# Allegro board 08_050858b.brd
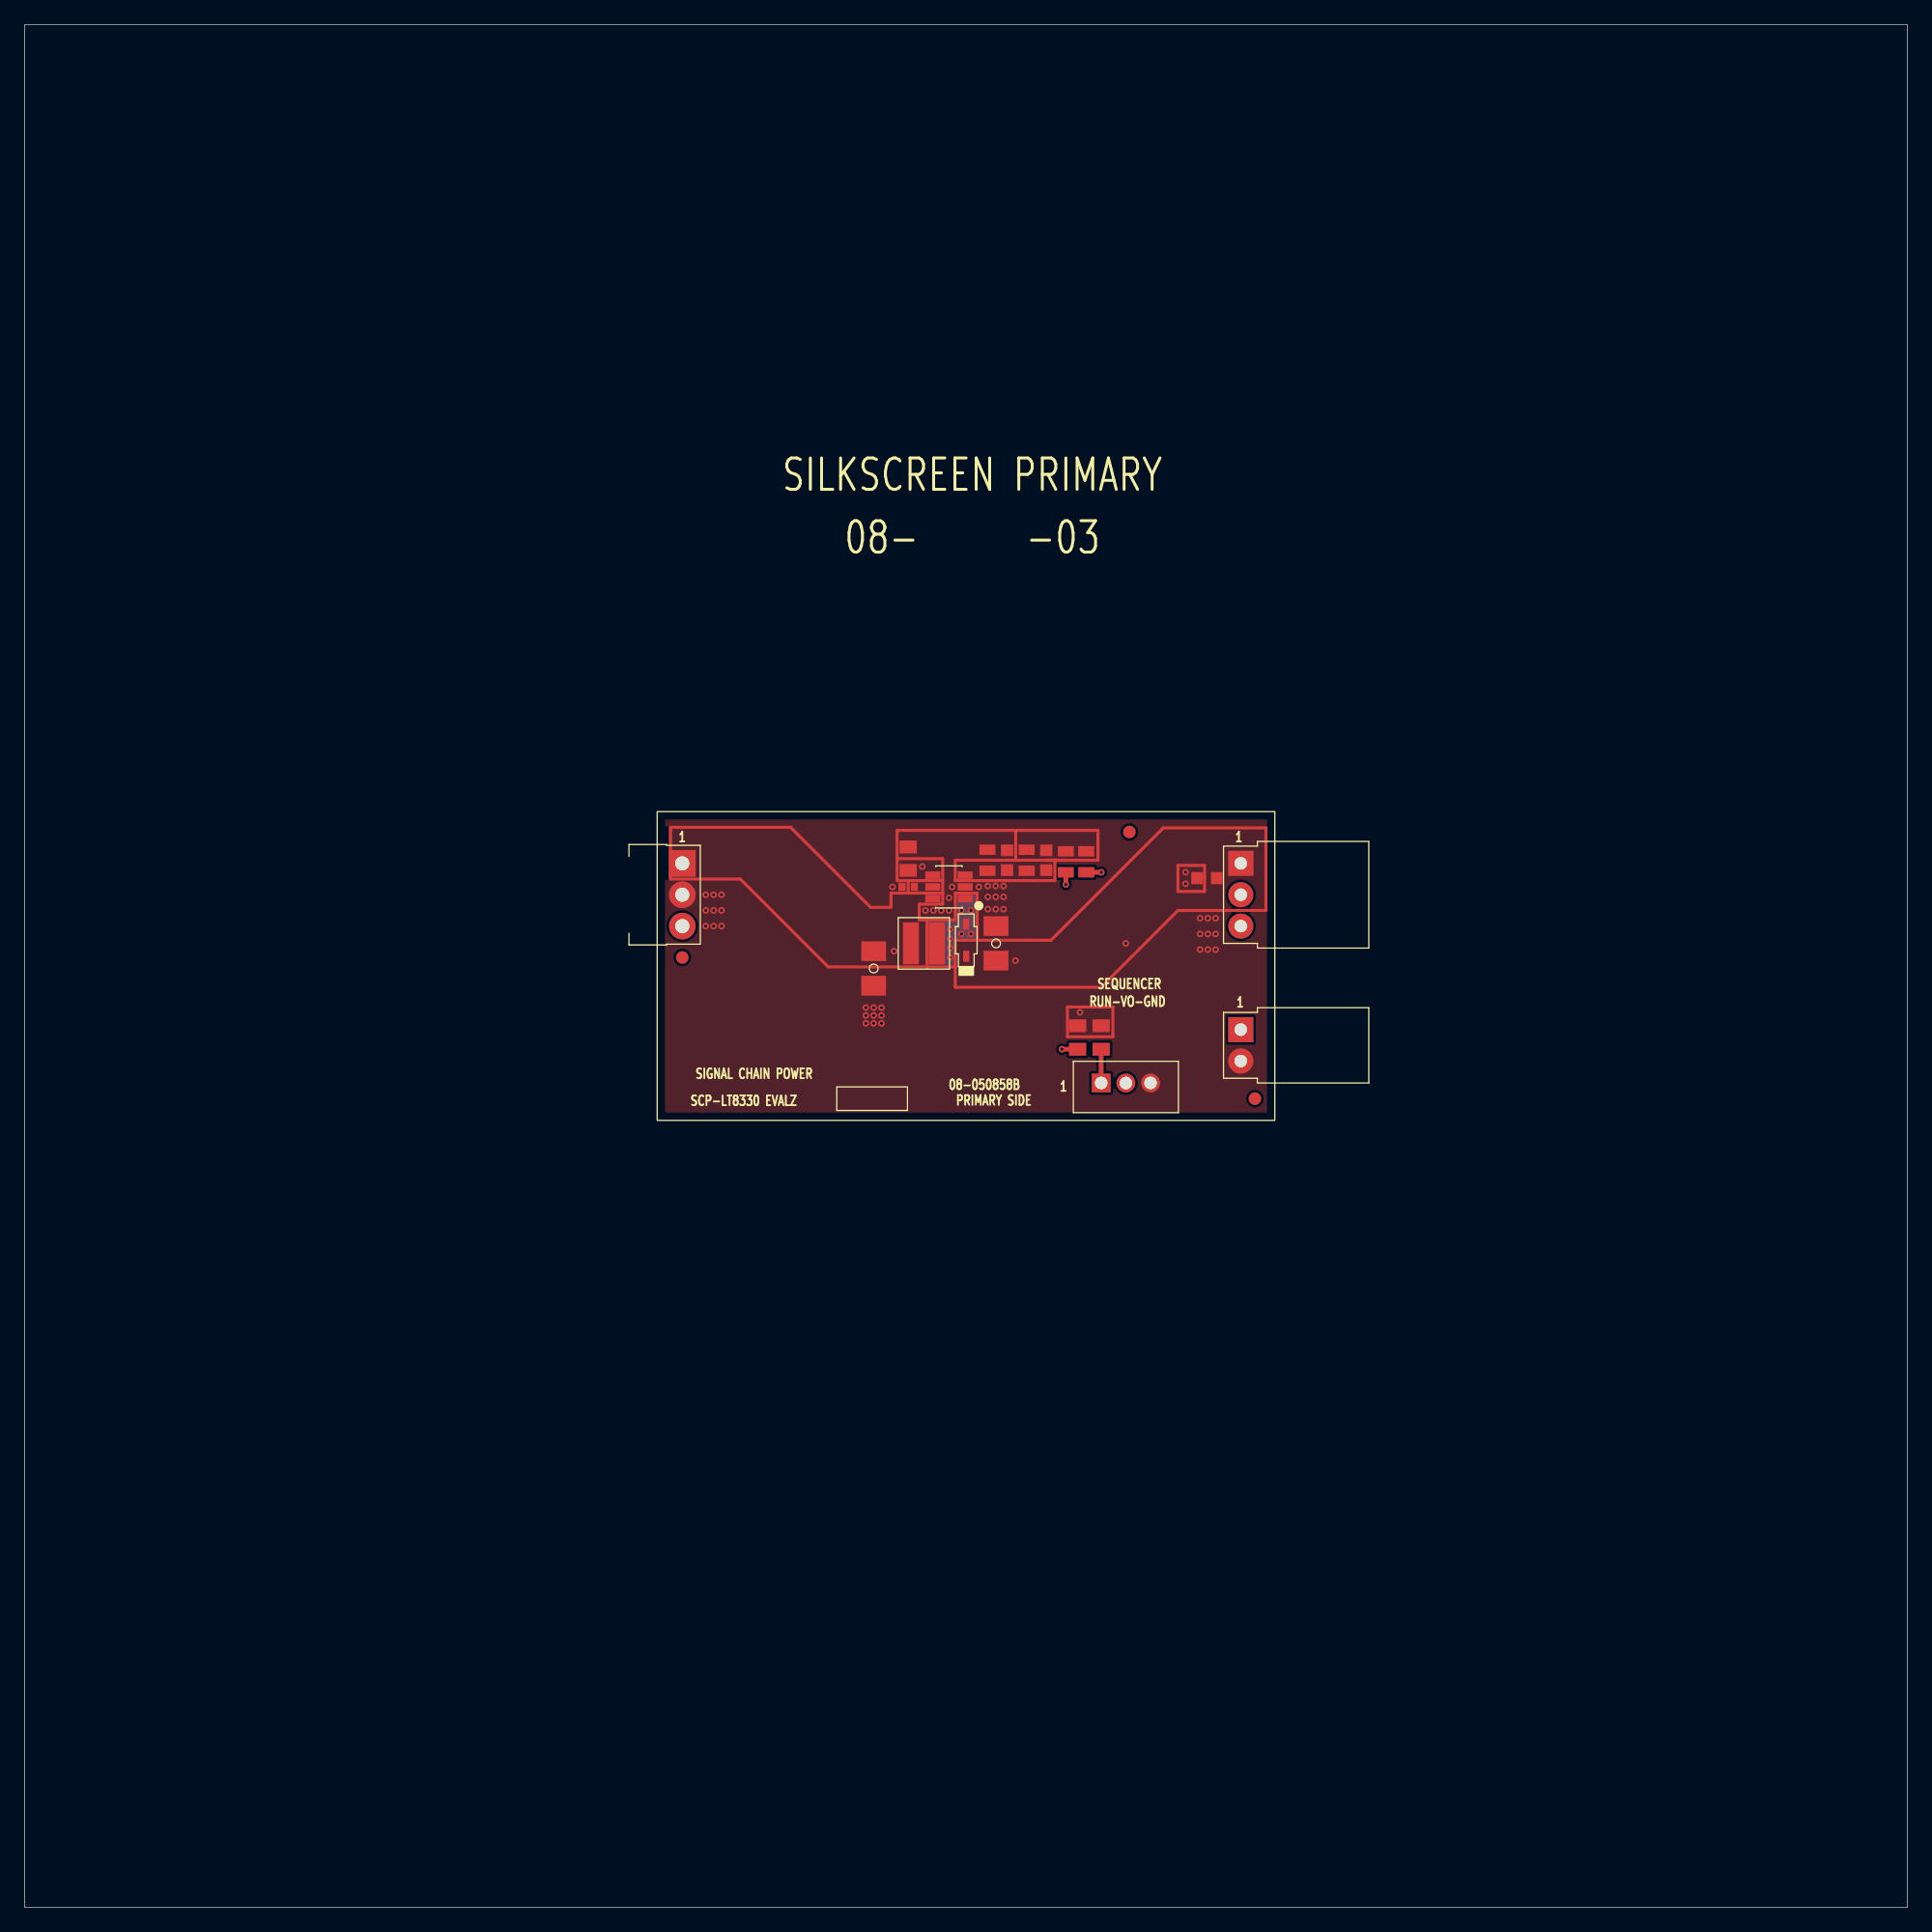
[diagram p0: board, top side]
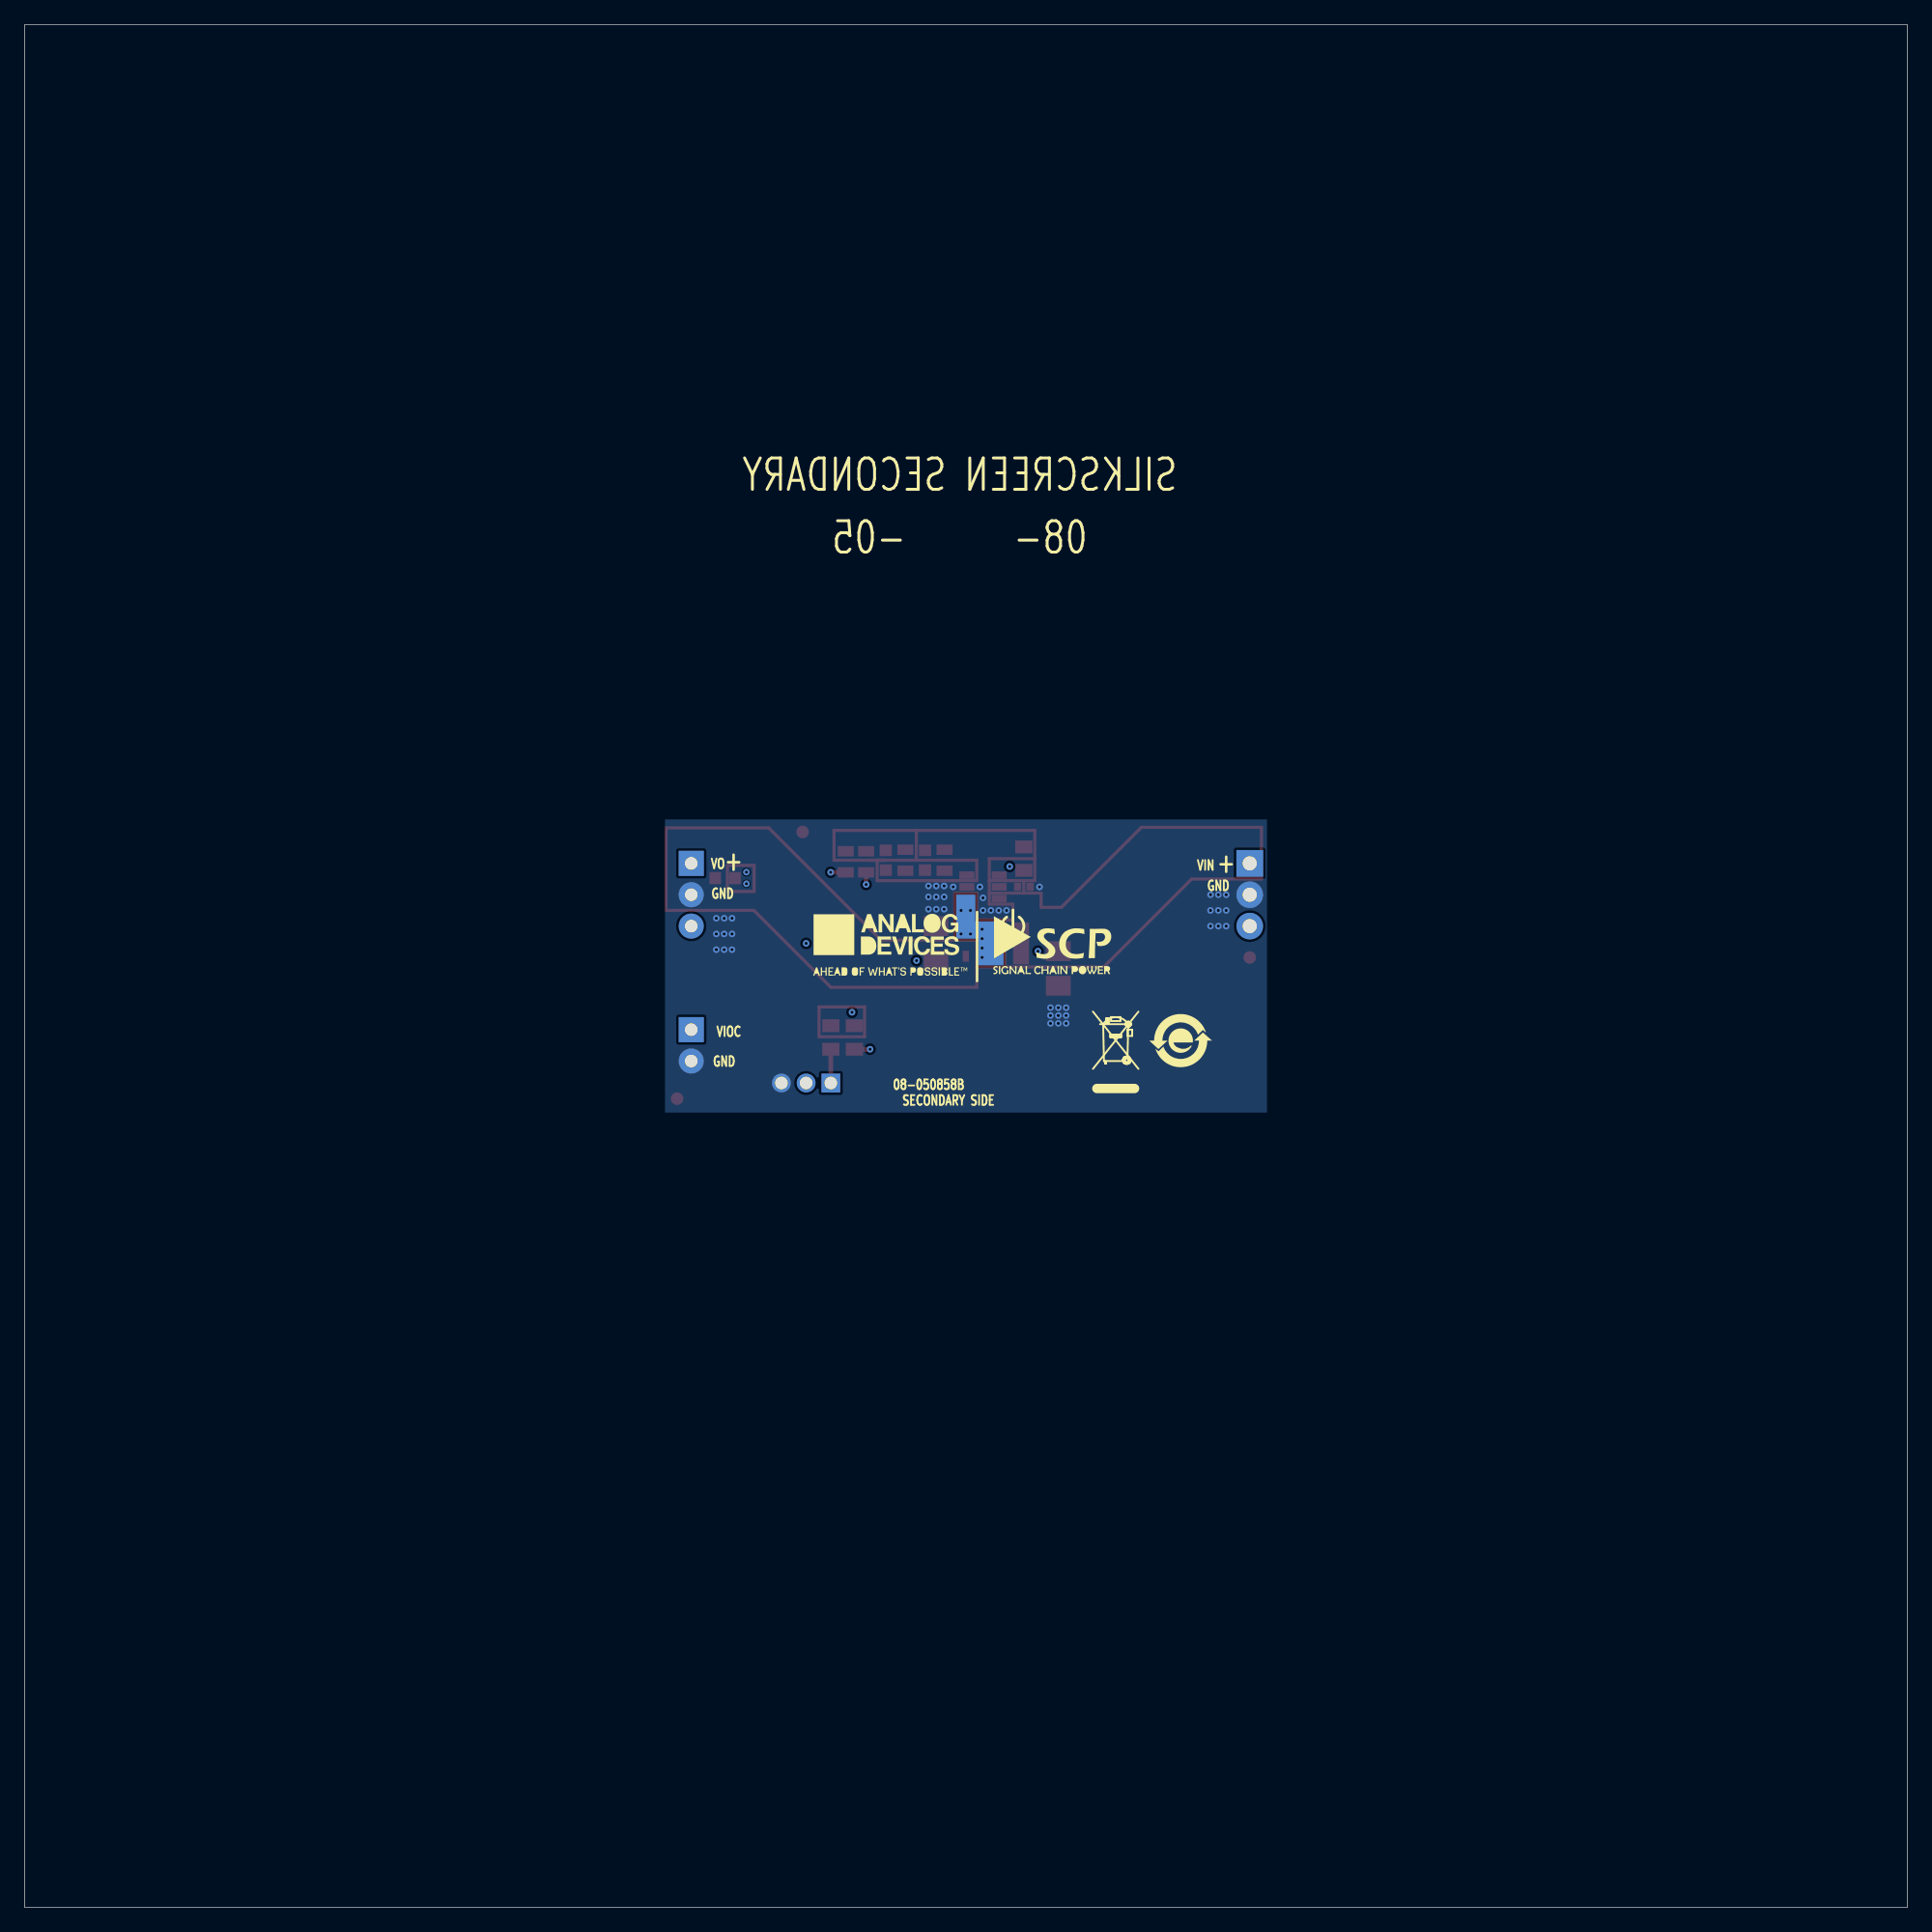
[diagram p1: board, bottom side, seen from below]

Outline 152.4 x 152.4 mm; copper layers: TOP, L2_AGND, L3_SIGNAL, BOTTOM. Coordinates in mm from the lower left corner of the outline.
Outline path: 0,152.4 152.4,152.4 152.4,0 0,0 0,152.4

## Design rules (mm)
constraint set DEFAULT: min track width 0.203

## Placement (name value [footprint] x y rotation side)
C1  4.7UF  [C1206H71]  68.73 76 270 top
C2  4.7UF  [C1206H71]  78.63 78.03 90 top
C3  1UF  [C0402]  71.52 82.6 180 top
C4  TBD0603  [C0603]  79.52 84.76 90 top
C8  4.7PF  [C0603]  82.7 84.76 270 top
C12  0.1UF  [C0603]  95.7 83.32 180 top
D1  PMEG6010CEJ  [SOD323F_B]  76.22 78.29 90 top
INPUT  PBC03SBAN  [CNTHMHDRRA1X3L300W100H145]  53.23 84.51 270 top
L1  6.8UH  [LSMSQ118H59_WE]  72.79 78.03 0 top
NOREF  -  []  101.19 63.71 90 top
NOREF#2  -  []  121.43 207.19 0 top
NOREF#3  -  []  51.18 88.77 270 top
NOREF#4  -  []  101.22 63.63 90 top
NOREF#5  -  []  51.18 63.63 0 top
NOREF#6  -  []  101.22 88.77 180 top
NOREF#7  -  [unnamed#2]  99.59 65.46 0 top
NOREF#8  -  []  -84.59 14.53 0 top
NOREF#9  -  []  -74.78 242.5 0 top
NOREF#10  -  []  -149.21 -137.49 0 top
NOREF#11  -  [unnamed#2]  53.23 76.89 0 top
NOREF#12  -  []  -298.45 -222.25 0 top
NOREF#13  -  []  76.71 109.73 0 top
NOREF#14  -  []  -298.45 -222.25 0 top
NOREF#15  -  []  51.2 63.71 0 top
NOREF#16  -  [unnamed#2]  89.43 87.05 0 top
NOREF#17  -  []  -176.08 -131.37 0 top
NOREF#18  -  []  141.99 96.01 0 top
NOREF#19  -  []  69.18 78.18 180 bottom
NOREF#20  -  []  58.82 70.16 180 bottom
NOREF#21  -  []  82.63 77.88 180 bottom
NOREF#22  -  []  64.28 65.97 180 bottom
OUTPUT  PPPC031LGBN-RC  [CNHDRRA1X3H108]  98.44 84.51 270 top
P1  53253-0370  [CNTHMHDR1X3L315W144H224]  87.14 66.73 0 top
R1  1MEG  [R0805#2]  81.11 84.76 270 top
R2  34.8K  [R0805#2]  77.93 84.76 90 top
R3  0  [R0805#2]  85.93 84.64 270 top
R5  1MEG  [R0805]  85.24 70.41 90 top
R6  215K  [R0805]  71.52 84.89 90 top
R7  0  [R0805]  87.14 70.41 90 top
R8  0  [R0805#2]  84.28 84.64 90 top
U1  LT8330ES6#PBF  [TSOT23_6]  74.82 82.6 90 top
VIOC  PPPC021LGBN-RC  [CNTHFHDRRA1X2L220W335H108]  98.44 71.05 270 top

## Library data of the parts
C1 C2 = CAP: Tolerance: 10; User Part Number: UPN; alternate symbols: (); part number: CAP_SM-4.7UF,50V,10,E038262,C1206H71; tolerance: 10
C3 = CAP: User Part Number: UPN; Tolerance: 10; alternate symbols: (); part number: CAP_SM-1UF,6.3V,10,E030593,C0402; tolerance: 10
C4 = CAP: User Part Number: UPN; alternate symbols: (C0603L, C0603L_ALT); part number: CAP_SM-TBD0603,TBD0603,TBD0603,E000382,C0603
C8 = CAP: User Part Number: UPN; Tolerance: 5; alternate symbols: (); part number: CAP_SM-4.7PF,50V,5,E000406,C0603; tolerance: 5
C12 = CAP: User Part Number: UPN; Tolerance: 10; alternate symbols: (); part number: CAP_SM-0.1UF,50V,10,E038267,C0603; tolerance: 10
D1 = DIOSCHOTTKY: User Part Number: UPN; Tolerance: N/A; alternate symbols: (); part number: DIOSCHOTTKY_SM-PMEG6010CEJ,60V,N/A,E033509,SOD323F_B; tolerance: N/A
INPUT = CN3P: Tolerance: N/A; User Part Number: UPN; alternate symbols: (CNTHMHDRRA1X3L300W100H145_SCP); part number: CN3P_TH-PBC03SBAN,E034137,CNTHMHDRRA1X3L300W100H145; tolerance: N/A
L1 = IND: User Part Number: UPN; Tolerance: 20; alternate symbols: (); part number: IND_SM-6.8UH,20,E033536,LSMSQ118H59_WE; tolerance: 20
OUTPUT = CN3P: User Part Number: UPN; Tolerance: N/A; alternate symbols: (CNHDRRA1X3H108_SCP); part number: CN3P_TH-PPPC031LGBN-RC,E034111,CNHDRRA1X3H108; tolerance: N/A
P1 = CN3P: Tolerance: N/A; User Part Number: UPN; alternate symbols: (); part number: CN3P_TH-53253-0370,E033940,CNTHMHDR1X3L315W144H224; tolerance: N/A
R1 = RES: User Part Number: UPN; Tolerance: 1; alternate symbols: (R0805L); part number: RES_SM-1MEG,E003518,1/8W,1,R0805; tolerance: 1
R2 = RES: User Part Number: UPN; Tolerance: 0.1; alternate symbols: (R0805L); part number: RES_SM-34.8K,E010465,1/10W,0.1,R0805; tolerance: 0.1
R3 R7 R8 = RES: User Part Number: UPN; Tolerance: N/A; alternate symbols: (R0805L); part number: RES_SM-0,E030875,1/8W,N/A,R0805; tolerance: N/A
R5 = RES: User Part Number: UPN; Tolerance: 5; alternate symbols: (); part number: RES_SM-1MEG,E033749,1/8W,5,R0805; tolerance: 5
R6 = RES: User Part Number: UPN; Tolerance: 1; alternate symbols: (); part number: RES_SM-215K,E033605,1/8W,1,R0805; tolerance: 1
U1 = LINLT8330: User Part Number: UPN; Tolerance: N/A; alternate symbols: (); part number: LINLT8330_SM-LT8330ES6#PBF,E033517,TSOT23_6; tolerance: N/A
VIOC = CN2P: Tolerance: N/A; User Part Number: UPN; alternate symbols: (CNTHFHDRRA1X2L220W335H108_SCP); part number: CN2P_TH-PPPC021LGBN-RC,E034113,CNTHFHDRRA1X2L220W335H108; tolerance: N/A

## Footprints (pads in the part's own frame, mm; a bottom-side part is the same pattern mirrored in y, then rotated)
C0402
  rect 0.584x0.66 smd: 1(-0.5,0) 2(0.5,0)
C0603
  rect 0.94x0.991 smd: 1(-0.8,0) 2(0.8,0)
C1206H71
  rect 1.6x2.007 smd: 1(-1.397,0) 2(1.397,0)
CNHDRRA1X3H108
  rect 2.032x2.032 hole 1.016: 1(0,0)
  round 2.032 hole 1.016: 2(2.54,0) 3(5.08,0)
CNTHFHDRRA1X2L220W335H108
  rect 2.032x2.032 hole 1.016: 1(0,0)
  round 2.032 hole 1.016: 2(2.54,0)
CNTHMHDR1X3L315W144H224
  rect 1.524x1.524 hole 1.016: 1(0,0)
  round 1.524 hole 1.016: 2(2,0) 3(4,0)
CNTHMHDRRA1X3L300W100H145
  rect 2.159x2.159 hole 1.143: 1(0,0)
  round 2.159 hole 1.143: 2(2.54,0) 3(5.08,0)
LSMSQ118H59_WE
  rect 1.295x3.404 smd: 1(-1.048,0) 2(1.048,0)
R0805
  rect 1.041x1.397 smd: 1(-0.95,0) 2(0.95,0)
R0805#2
  rect 0.838x1.295 smd: 1(-0.85,0) 2(0.85,0)
SOD323F_B
  rect 0.889x0.508 smd: A(1.3,0) C(-1.3,0)
TSOT23_6
  rect 0.61x1.219 smd: 1(-0.95,-1.31) 2(0,-1.31) 3(0.95,-1.31) 4(0.95,1.31) 5(0,1.31) 6(-0.95,1.31)
unnamed#2
  round 1.016 smd: (0,0)

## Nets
GND: C1.2(N2) C2.2(N2) C3.2(N2) C4.2(N2) C12.2(N2) INPUT.2 OUTPUT.2 P1.3(N3) R2.2(N2) R6.2(N2) U1.2 VIOC.2(N2)
RUN: P1.1 R7.1
UNNAMED_2_CAP_I6_N1: C3.1 U1.5
UNNAMED_2_CAP_I12_N1: C8.1 R1.1 R3.1 R8.2(N2)
UNNAMED_2_CAP_I12_N2: C4.1 C8.2(N2) R1.2(N2) R2.1 U1.3
UNNAMED_2_DIOSCHOTTKY_I13_P: D1.A(P) L1.2(N2) U1.1
UNNAMED_2_LINLT8330_I20_ENN: R5.2(N2) R6.1 R7.2(N2) U1.4
V+: C1.1 INPUT.1 L1.1 R5.1 U1.6(VIN)
VIOC: R3.2(N2) VIOC.1
VO+: C2.1 C12.1 D1.C OUTPUT.1 P1.2 R8.1

Pads without a net: INPUT 3; OUTPUT 3

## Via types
v1: diameter 0.533, hole 0.254, TOP to BOTTOM, 62 vias

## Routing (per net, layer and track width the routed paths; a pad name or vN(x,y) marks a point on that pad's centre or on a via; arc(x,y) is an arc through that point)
GND: length 0
  vias: v1(55.14,81.97) v1(55.14,80.7) v1(55.14,79.43) v1(55.77,81.97) v1(55.77,80.7) v1(55.77,79.43) v1(56.41,81.97) v1(56.41,80.7) v1(56.41,79.43) v1(68.09,72.83) v1(68.09,72.19) v1(68.09,71.56) v1(68.73,72.83) v1(68.73,72.19) v1(68.73,71.56) v1(69.36,72.83) v1(69.36,72.19) v1(69.36,71.56) v1(70.25,82.6) v1(72.92,80.7) v1(73.55,80.7) v1(74.19,80.7) v1(74.82,81.72) v1(74.82,80.7) v1(75.08,82.6) v1(77.24,82.6) v1(77.97,82.68) v1(77.97,81.79) v1(77.97,80.8) v1(78.61,82.68) v1(78.61,81.79) v1(78.61,80.8) v1(79.24,82.68) v1(79.24,81.79) v1(79.24,80.8) v1(93.97,83.8) v1(93.97,82.86) v1(95.14,80.06) v1(95.14,78.79) v1(95.14,77.52) v1(95.78,80.06) v1(95.78,78.79) v1(95.78,77.52) v1(96.41,80.06) v1(96.41,78.79) v1(96.41,77.52)
RUN: length 2.7
  TOP w0.381: R7.1 P1.1
UNNAMED_2_DIOSCHOTTKY_I13_P:
  vias: v1(74.9,79.18) v1(74.9,78.41) v1(74.9,77.65) v1(74.9,76.89) v1(75.84,80.7) v1(75.84,78.79) v1(76.6,80.7) v1(76.6,78.79)
UNNAMED_2_LINLT8330_I20_ENN: length 24
  L3_SIGNAL w0.381: v1(72.66,84.26) 84.41,84.26 85.43,83.24 v1(85.43,72.45)
V+: length 19.7
  TOP w0.381: R5.1 v1(83.97,69.46)
  L3_SIGNAL w0.381: v1(83.97,69.46) 75.59,69.46 70.38,74.68 v1(70.38,77.4)
VIOC: length 18.6
  TOP w0.381: R3.2 v1(87.15,83.79)
  L3_SIGNAL w0.381: VIOC.1 98.44,72.5 v1(87.15,83.79)
VO+: length 20.1
  TOP w0.381: R8.1 v1(84.28,82.8)
  L3_SIGNAL w0.381: P1.2 v1(89.14,78.03) ; v1(80.21,76.64) 84.28,80.71 v1(84.28,82.8)

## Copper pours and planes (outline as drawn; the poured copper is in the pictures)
GND on TOP: 51.84,88.06 100.56,88.06 100.56,87.51 92.12,87.51 83.02,78.41 77.24,78.41 77.24,82.22 75.2,82.22 75.2,80.06 72.54,80.06 72.54,81.08 74.44,81.08 74.44,85.02 70.76,85.02 70.76,87.05 80.09,87.05 80.09,84.89 75.2,84.89 75.2,83.06 75.28,82.99 83.52,82.99 83.52,84.64 87.01,84.64 87.01,87.3 70.5,87.3 70.5,82.99 71.39,82.99 71.39,82.22 70,82.22 70,81.08 68.52,81.08 62.05,87.56 52.14,87.56 52.14,83.11 57.88,83.11 64.99,76 75.2,76 75.2,74.35 87.19,74.35 93.42,80.57 100.56,80.57 100.56,64.34 51.84,64.34 ; 1 cut-out
GND on TOP: 93.48,84.22 95.38,84.22 95.38,82.36 93.48,82.36
GND on BOTTOM: 51.84,88.06 100.56,88.06 100.56,64.34 51.84,64.34 ; 3 cut-outs
GND on L2_AGND: 51.84,88.06 100.56,88.06 100.56,87.48 92.09,87.48 83.02,78.41 80.16,78.41 80.16,79.94 80.08,80.01 79.98,80.01 79.9,79.94 79.9,78.16 83.13,78.16 92.2,87.23 100.35,87.23 100.35,80.83 93.34,80.83 87.11,74.6 75.46,74.6 75.46,78.16 77.24,78.16 77.24,82.17 75.25,82.17 75.25,80.04 72.97,80.04 72.97,76.03 75.2,76.03 75.2,74.35 87.06,74.35 87.09,74.32 87.19,74.32 93.44,80.57 100.56,80.57 100.56,64.34 51.84,64.34
GND on L3_SIGNAL: 51.84,88.06 100.56,88.06 100.56,64.34 51.84,64.34 ; 3 cut-outs
UNNAMED_2_CAP_I6_N1 on TOP: 71.65,82.99 74.19,82.99 74.19,82.22 71.65,82.22
UNNAMED_2_CAP_I12_N1 on TOP: 80.35,87.05 86.76,87.05 86.76,84.89 80.35,84.89
UNNAMED_2_CAP_I12_N2 on TOP: 75.46,84.64 83.27,84.64 83.27,83.24 75.46,83.24
UNNAMED_2_DIOSCHOTTKY_I13_P on BOTTOM (solid shape): 76.98,78.41 75.2,78.41 75.2,76.25 73.17,76.25 73.17,79.81 75.46,79.81 75.46,81.97 76.98,81.97
UNNAMED_2_DIOSCHOTTKY_I13_P on L3_SIGNAL (solid shape): 76.98,78.41 75.2,78.41 75.2,76.25 73.17,76.25 73.17,79.81 75.46,79.81 75.46,81.97 76.98,81.97
UNNAMED_2_DIOSCHOTTKY_I13_P on TOP: 75.46,81.97 76.98,81.97 76.98,78.41 75.2,78.41 75.2,76.25 73.17,76.25 73.17,79.81 75.46,79.81
UNNAMED_2_DIOSCHOTTKY_I13_P on L2_AGND: 75.51,81.92 76.98,81.92 76.98,78.41 75.28,78.41 75.2,78.34 75.2,76.28 73.22,76.28 73.22,79.78 75.51,79.78
UNNAMED_2_LINLT8330_I20_ENN on TOP: 84.54,72.76 87.97,72.76 87.97,70.6 84.54,70.6
UNNAMED_2_LINLT8330_I20_ENN on TOP: 70.76,84.76 74.19,84.76 74.19,83.24 70.76,83.24
V+ on TOP: 52.14,87.3 61.94,87.3 68.42,80.83 70.25,80.83 70.25,81.97 74.19,81.97 74.19,81.33 72.28,81.33 72.28,79.81 72.92,79.81 72.92,76.25 65.1,76.25 57.98,83.37 52.14,83.37
VO+ on TOP: 92.22,87.25 100.35,87.25 100.35,80.83 93.31,80.83 87.09,74.6 75.46,74.6 75.46,78.16 82.97,78.16 83,78.13 83.1,78.13 ; 1 cut-out

Small or netless copper shapes (teardrops, artwork), in the pictures only: 1 on L3_SIGNAL

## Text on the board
Ref Des/Silkscreen Bottom: GND | VIN | SECONDARY SIDE | 08-050858B | VIOC | VO | +
User.Comments: 4.    RoHS COMPLIANCE: ASSEMBLY VENDOR SHOULD ASSURE COMPLIANCE | WITH LEAD-FREE AND RoHS PCB ASSEMBLY STANDARDS (EU RoHS | DIRECTIVE 2002/95/EC).
Ref Des/Silkscreen Top: SCP-LT8330 EVALZ | SIGNAL CHAIN POWER | 08-050858B | PRIMARY SIDE | RUN-VO-GND | SEQUENCER
PAGE_OUTLINE: B | AS PER ECR-086391 | 06MAY19 | J VIERNES
DIMENSION: REF | -0.819 | 0.165 | "0" | SEE FAB NOTE 15 | DIA MAX | -0.80 | 1.889
User.15: ROHS COMPLIANCE NOTE: | ENIG (Electroless Nickel/Immersion Gold) | PER IPC-4552 LATEST REVISION | HOMOGENOUS MATERIALS IN THIS BOARD SHALL BE COMPLIANT | THE EU RoHS DIRECTIVE 2002/95/EC | 15.    THRU VIAS TO BE FILLED WITH SOLDERMASK. | 0.035"
User.17: L2 | 08-      -07
User.18: L3 | 08-      -08
User.45: FIGURE | SIZE | 10.0 | 40.0 | 45.0 | PLATED | FINISHED HOLES IN MILS | ALL UNITS ARE IN MILS | QTY | 62 | 8 | 3 | TOLERANCE/NOTES
